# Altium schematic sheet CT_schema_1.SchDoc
size 466 x 258 mm
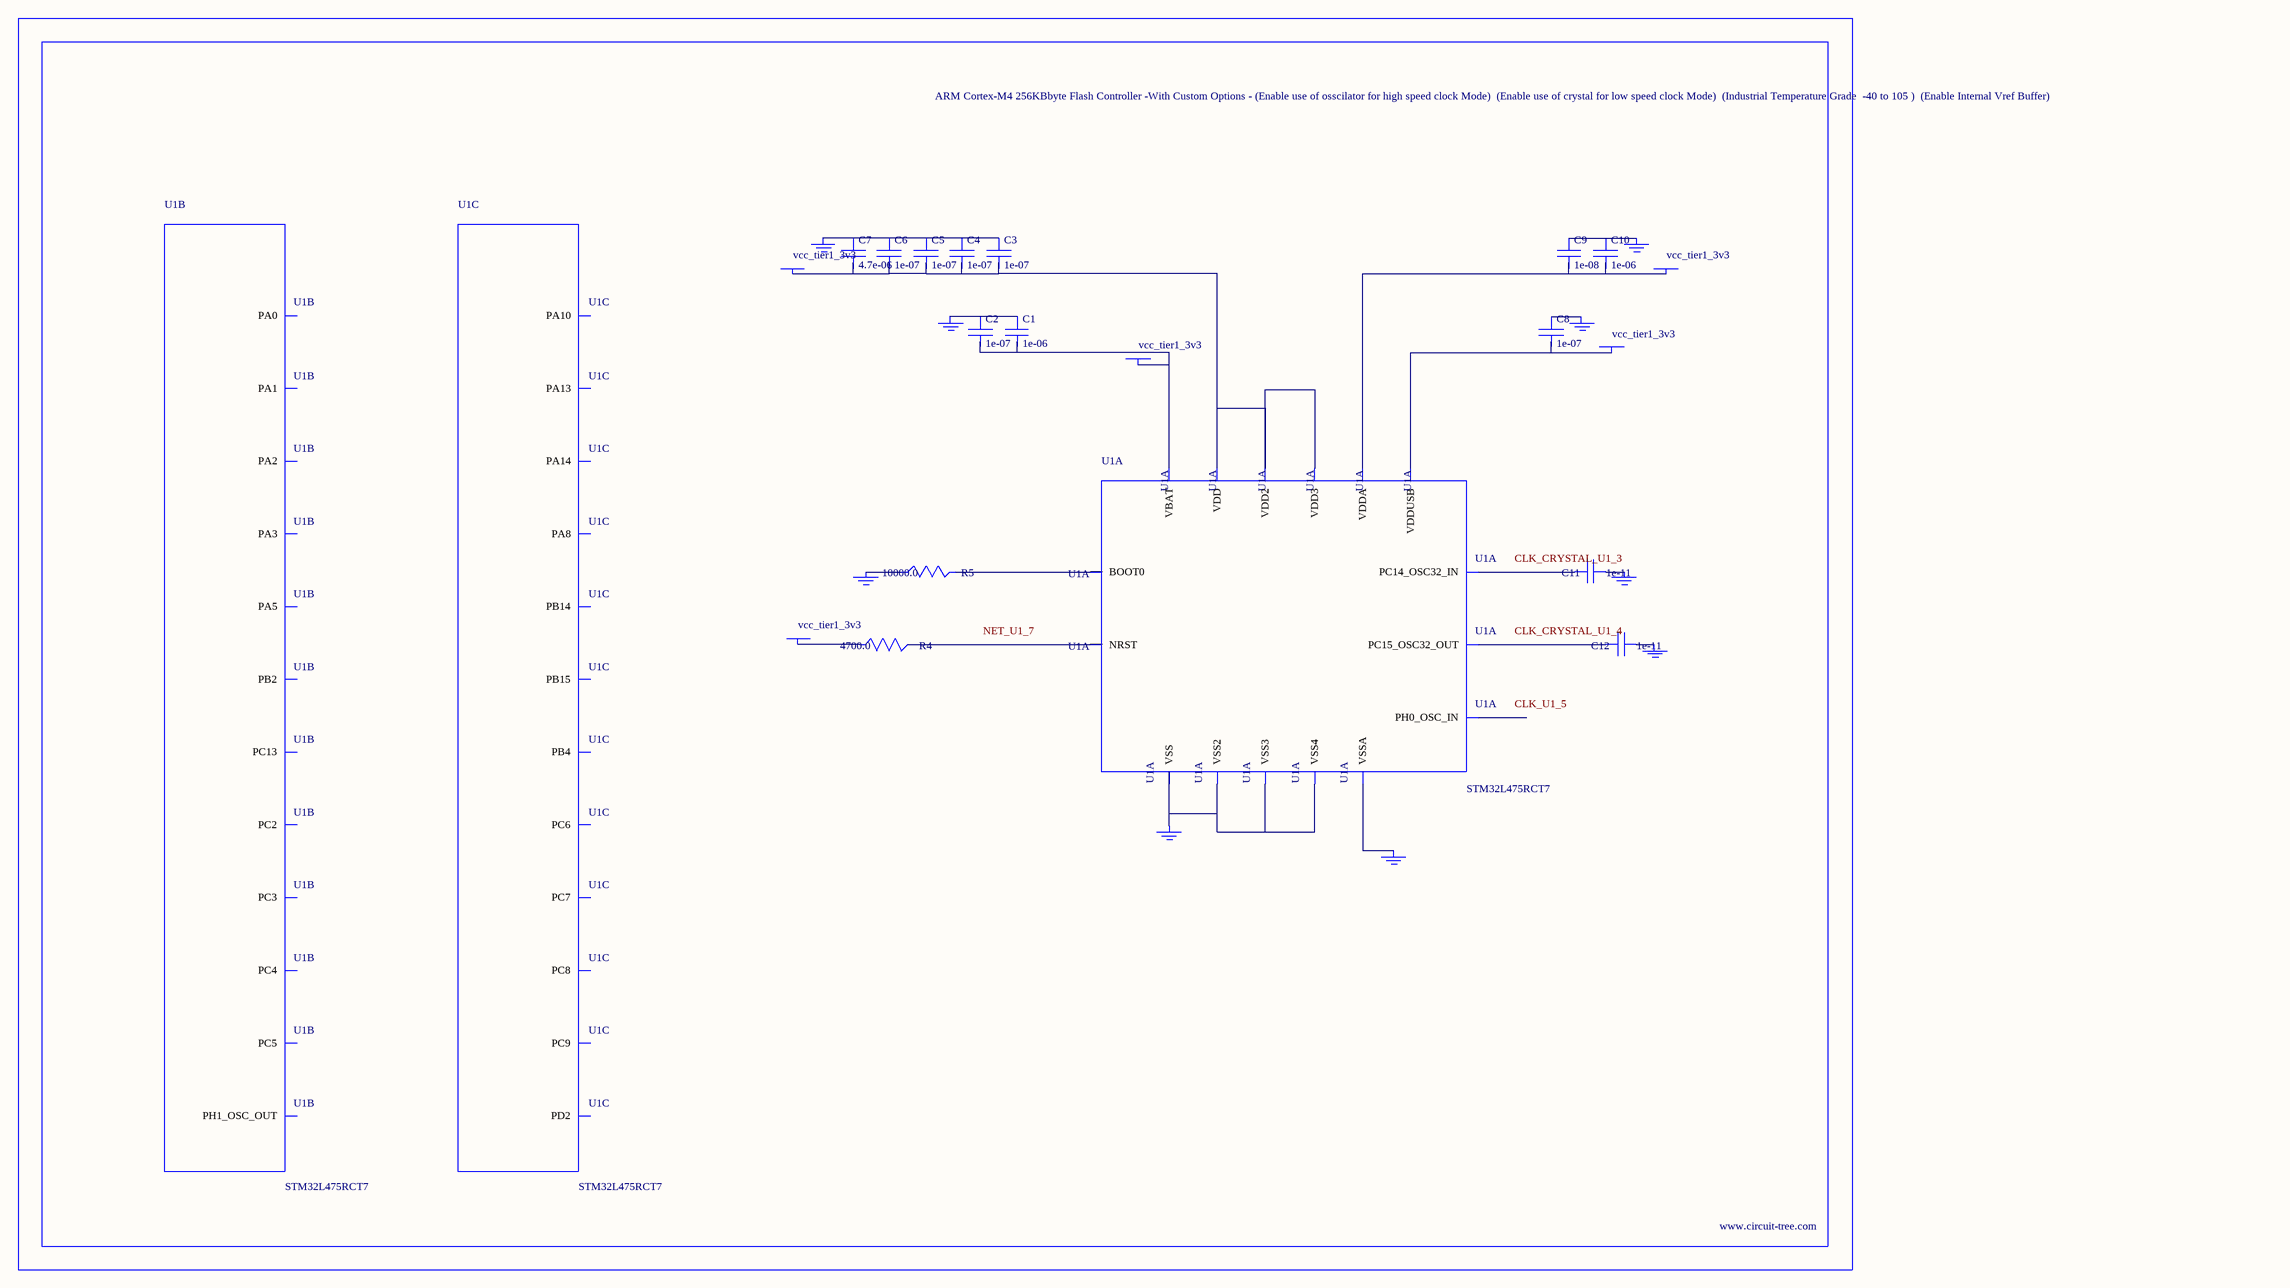
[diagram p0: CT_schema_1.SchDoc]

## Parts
BORDER0  (no value)
C1  1e-06  [C0603]
C2  1e-07  [C0603]
C3  1e-07  [C0603]
C4  1e-07  [C0603]
C5  1e-07  [C0603]
C6  1e-07  [C0603]
C7  4.7e-06  [C0603]
C8  1e-07  [C0603]
C9  1e-08  [C0603]
C10  1e-06  [C0603]
C11  1e-11  [C0402]
C12  1e-11  [C0402]
GND_INSTANCE_0_0  (no value)
GND_INSTANCE_0_1  (no value)
GND_INSTANCE_0_2  (no value)
GND_INSTANCE_0_3  (no value)
GND_INSTANCE_0_4  (no value)
GND_INSTANCE_0_5  (no value)
GND_INSTANCE_0_6  (no value)
GND_INSTANCE_0_7  (no value)
GND_INSTANCE_0_8  (no value)
POWER_INSTANCE_0_0  vcc_tier1_3v3
POWER_INSTANCE_0_1  vcc_tier1_3v3
POWER_INSTANCE_0_2  vcc_tier1_3v3
POWER_INSTANCE_0_3  vcc_tier1_3v3
POWER_INSTANCE_0_4  vcc_tier1_3v3
R4  4700.0  [R0603]
R5  10000.0  [R0603]
U1  STM32L475RCT7  [LQFP64]  (parts A,B,C of 8)

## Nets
NetC1_1: C1.1 C2.1 GND_INSTANCE_0_0.0(GND)
NetC1_2: C1.2 C2.2 POWER_INSTANCE_0_0.0(PWR) U1.1(VBAT)
NetC3_1: C3.1 C4.1 C5.1 C6.1 C7.1 GND_INSTANCE_0_5.0(GND)
NetC3_2: C3.2 C4.2 C5.2 C6.2 C7.2 POWER_INSTANCE_0_2.0(PWR) U1.19(VDD) U1.32(VDD2) U1.64(VDD3)
NetC8_1: C8.1 GND_INSTANCE_0_6.0(GND)
NetC8_2: C8.2 POWER_INSTANCE_0_3.0(PWR) U1.48(VDDUSB)
NetC9_1: C9.1 C10.1 GND_INSTANCE_0_4.0(GND)
NetC9_2: C9.2 C10.2 POWER_INSTANCE_0_1.0(PWR) U1.13(VDDA)
NetC11_1: C11.1 GND_INSTANCE_0_1.0(GND)
NetC11_2: C11.2 U1.3(PC14_OSC32_IN)
NetC12_1: C12.1 GND_INSTANCE_0_2.0(GND)
NetC12_2: C12.2 U1.4(PC15_OSC32_OUT)
NetGND_INSTANCE_0_3_0: GND_INSTANCE_0_3.0(GND) U1.12(VSSA)
NetGND_INSTANCE_0_7_0: GND_INSTANCE_0_7.0(GND) R5.1
NetGND_INSTANCE_0_8_0: GND_INSTANCE_0_8.0(GND) U1.18(VSS) U1.31(VSS2) U1.47(VSS3) U1.63(VSS4)
NetPOWER_INSTANCE_0_4_0: POWER_INSTANCE_0_4.0(PWR) R4.1
NetR4_2: R4.2 U1.7(NRST)
NetR5_2: R5.2 U1.60(BOOT0)

Not connected (* = marked no-connect by the designer): U1 2(PC13) 5(PH0_OSC_IN) 6(PH1_OSC_OUT) 10(PC2) 11(PC3) 14(PA0) 15(PA1) 16(PA2) 17(PA3) 21(PA5) 24(PC4) 25(PC5) 28(PB2) 35(PB14) 36(PB15) 37(PC6) 38(PC7) 39(PC8) 40(PC9) 41(PA8) 43(PA10) 46(PA13) 49(PA14) 54(PD2) 56(PB4)

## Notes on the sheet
- Labels drawn without touching a wire or pin: CLK_CRYSTAL_U1_3, CLK_CRYSTAL_U1_4, CLK_U1_5, NET_U1_7

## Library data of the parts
BORDER0 = BORDER_PAGE0
C1 C10 = C0603C105K3RACTU
C2-C6 C8 = 06035C104K4Z2A
C7 = GRM188R6YA475KE15D
C9 = 06035C103K4Z2A
C11 C12 = C0402C100K3GACTU
GND_INSTANCE_0_0-GND_INSTANCE_0_8 = GND
POWER_INSTANCE_0_0-POWER_INSTANCE_0_4 = PWR
R4 = RC0603JR-074K7L
R5 = RC0603JR-0710KL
